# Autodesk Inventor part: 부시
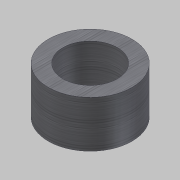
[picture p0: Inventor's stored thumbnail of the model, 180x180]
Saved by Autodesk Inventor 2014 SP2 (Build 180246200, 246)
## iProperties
Company: 한국ATC센터
Created: 2014-10
Part Number: 부시
Document SubType Name: Modeling
Designer: 한국ATC센터
Density: 7.86 g/cm^3
Material: 강철, 연강
Mass: 157.788 g
Surface Area: 70.2617 cm^2
Volume: 20.0748 cm^3
Appearance: 금속-강(기계 가공_02)
Author: KYOUNG IL JANG
Revision Number: 1
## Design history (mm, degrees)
sketch "스케치1"
  geometry: C1 r 21.5 at (0, 0) reference; C2 r 31 at (0, 0) reference; C3 r 14 at (0, 0) reference; 1 further point
  node "참조1"
  node "참조2"
node "작업 평면1"
extrude "돌출1" new body sketch "스케치1" stored distance "d0" = 10; taper "d1" = 0 deg
node "솔리드1"
